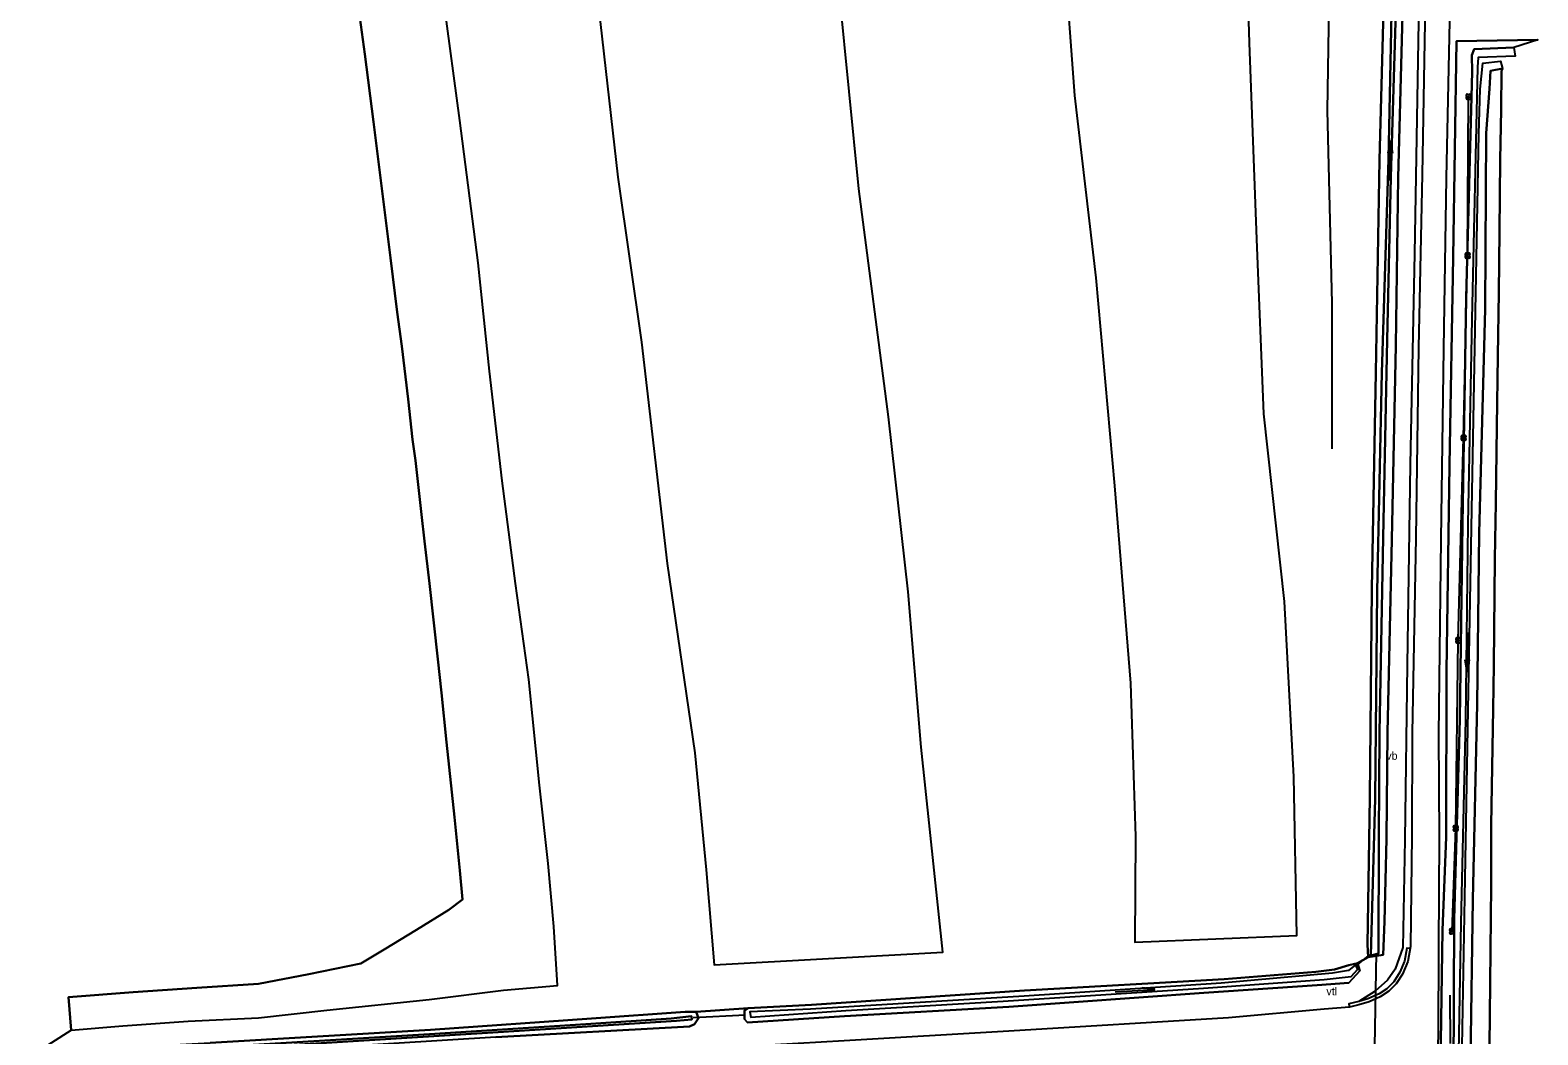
# Model space of a CAD drawing. Extents: x 154825 to 158680, y 370717 to 378075.
# Drawn here: x 157111.2 to 157300.9, y 373273.9 to 373400.2 of the extents above; entities that cross this region are included whole.
import ezdxf

# ---------------------------------------------------------------- set-up
doc = ezdxf.new("R2010")
doc.units = 0
for name, color, linetype in [('boom', 7, 'Continuous'), ('cultuurscheiding', 7, 'Continuous'), ('duiker lijn', 7, 'Continuous'), ('greppel - midden sloot', 7, 'Continuous'), ('hoogteverschillijn', 7, 'Continuous'), ('insteek sloot', 7, 'Continuous'), ('kant onverhard', 7, 'Continuous'), ('maaiveldlijn algemeen - gesloten verharding', 7, 'Continuous'), ('maaiveldlijn algemeen - onverhard', 7, 'Continuous'), ('maaiveldlijn algemeen - verharding algemeen', 7, 'Continuous'), ('raster - hek', 7, 'Continuous'), ('Sloot bodem', 7, 'Continuous'), ('stroomrichting  watergangen', 7, 'Continuous'), ('verkeersb_z kabel', 7, 'Continuous'), ('verklikker transportleiding', 7, 'Continuous'), ('vlak_Bos', 7, 'Continuous'), ('vlak_Grasland', 7, 'Continuous'), ('vlak_Grazige_vegetatie', 7, 'Continuous')]:
    doc.layers.add(name, color=color, linetype=linetype)

msp = doc.modelspace()

# ---------------------------------------------------------------- linework, layer by layer
at = {"layer": 'boom'}
msp.add_lwpolyline([(157290.1, 373286.89), (157290.56, 373299.85), (157290.88, 373323.49), (157291.54, 373348.96), (157292.04, 373371.87), (157292.18, 373391.83)], dxfattribs=at)
for centre in [(157292.18, 373391.83), (157292.04, 373371.87), (157291.54, 373348.96), (157290.88, 373323.49), (157290.56, 373299.85), (157290.1, 373286.89)]:
    msp.add_circle(centre, 0.006, dxfattribs=at)
for centre, start, end in [((157292.02, 373391.99), 357.075, 272.925), ((157292.02, 373391.67), 87.075, 2.925), ((157292.33, 373391.99), 267.075, 182.925), ((157292.33, 373391.67), 177.075, 92.925), ((157291.88, 373372.03), 357.075, 272.925), ((157292.2, 373372.03), 267.075, 182.925), ((157291.88, 373371.71), 87.075, 2.925), ((157292.2, 373371.71), 177.075, 92.925), ((157291.39, 373349.11), 357.075, 272.925), ((157291.39, 373348.8), 87.075, 2.925), ((157291.7, 373349.11), 267.075, 182.925), ((157291.7, 373348.8), 177.075, 92.925), ((157290.72, 373323.64), 357.075, 272.925), ((157290.72, 373323.33), 87.075, 2.925), ((157291.04, 373323.64), 267.075, 182.925), ((157291.04, 373323.33), 177.075, 92.925), ((157290.4, 373300.01), 357.075, 272.925), ((157290.71, 373300.01), 267.075, 182.925), ((157290.4, 373299.69), 87.075, 2.925), ((157290.71, 373299.69), 177.075, 92.925), ((157289.94, 373287.04), 357.075, 272.925), ((157289.94, 373286.73), 87.075, 2.925), ((157290.26, 373287.04), 267.075, 182.925), ((157290.26, 373286.73), 177.075, 92.925)]:
    msp.add_arc(centre, 0.158, start, end, dxfattribs=at)
at = {"layer": 'cultuurscheiding'}
for points in [[(157278.21, 373282.9), (157279.55, 373283.66)], [(157195.01, 373276.76), (157201.55, 373277.22)]]:
    msp.add_lwpolyline(points, dxfattribs=at)
at = {"layer": 'duiker lijn'}
for points in [[(157278.13, 373282.65), (157279.76, 373283.94)], [(157280.53, 373284.15), (157280.26, 373267.78)], [(157194.64, 373276.06), (157201.22, 373276.41)]]:
    msp.add_lwpolyline(points, dxfattribs=at)
at = {"layer": 'greppel - midden sloot'}
msp.add_lwpolyline([(157298.05, 373396.94), (157293.38, 373396.78), (157293.28, 373395.57), (157292.56, 373363.86), (157292.07, 373338.15), (157291.77, 373313.51), (157291.19, 373287.95), (157290.87, 373269.37), (157291.07, 373268.84), (157291.29, 373269.01), (157291.34, 373270.07), (157291.71, 373291.21), (157292.12, 373314.73), (157292.52, 373337.62), (157293.03, 373364.87), (157293.47, 373387.19), (157293.64, 373392.8), (157293.98, 373396.06), (157296.17, 373396.31)], dxfattribs=at)
at = {"layer": 'hoogteverschillijn'}
for points in [[(157241.3, 373409.56), (157242.61, 373392), (157245.26, 373369.07), (157247.63, 373342.93), (157249.65, 373318.12), (157250.28, 373298.8), (157250.18, 373285.54), (157270.58, 373286.38), (157270.18, 373306.31), (157269.01, 373328.39), (157266.42, 373351.96), (157265.53, 373373.94), (157264.63, 373398.61), (157263.96, 373418.94)], [(157274.77, 373413.84), (157274.4, 373390.12), (157274.98, 373365.89), (157274.98, 373347.57)], [(157182.49, 373405.01), (157185.13, 373381.74), (157188.11, 373360.96), (157191.34, 373333.16), (157194.82, 373309.34), (157196.25, 373294.62), (157197.28, 373282.69), (157226.05, 373284.26), (157223.31, 373310.05), (157221.69, 373329.59), (157219.18, 373351.58), (157215.47, 373380.26), (157213.05, 373404.79)], [(157152.57, 373402.71), (157153.3, 373397.18), (157154.39, 373388.68), (157155.06, 373383.32), (157155.67, 373378.62), (157156.54, 373371.57), (157157.39, 373364.73), (157157.96, 373360.46), (157158.78, 373353.8), (157159.33, 373348.72), (157159.68, 373346.11), (157160.45, 373339.33), (157160.84, 373335.95), (157161.47, 373330.62), (157162.49, 373321.12), (157162.97, 373316.88), (157163.6, 373310.69), (157164.6, 373301.26), (157165.27, 373294.54), (157165.62, 373290.91), (157163.89, 373289.62), (157159.83, 373287.09), (157155.77, 373284.61), (157152.83, 373282.84), (157146.29, 373281.53), (157139.93, 373280.29), (157132.17, 373279.79), (157124.19, 373279.25), (157116.04, 373278.63), (157116.39, 373274.47), (157122.88, 373275.03), (157131.11, 373275.61), (157139.95, 373276.02), (157148.55, 373276.98), (157161.42, 373278.32), (157170.77, 373279.48), (157177.55, 373280.08), (157177.11, 373287.49), (157176.37, 373295.44), (157175.3, 373305.29), (157173.93, 373318.57), (157172.26, 373330.64), (157170.59, 373343.54), (157169.01, 373357.35), (157167.56, 373370.95), (157165.25, 373388.84), (157163.28, 373403.5)], [(157294.61, 373258.61), (157294.78, 373268.51), (157294.87, 373280.38), (157295.03, 373292.71), (157295.02, 373300.3), (157295.28, 373314.85), (157295.34, 373320.37), (157295.49, 373333.72), (157295.6, 373340.78), (157295.71, 373350.39), (157295.85, 373359.25), (157295.98, 373367.24), (157296.05, 373374.89), (157296.16, 373383.91), (157296.28, 373390.24), (157296.3, 373395.09)]]:
    msp.add_lwpolyline(points, dxfattribs=at)
at = {"layer": 'insteek sloot'}
for points in [[(157279.55, 373283.66), (157279.46, 373285.25), (157279.73, 373303.74), (157280, 373329.98), (157280.52, 373357.16), (157280.95, 373383.91), (157281.66, 373410.57)], [(157283.92, 373403.67), (157283.31, 373381.69), (157283, 373360.55), (157282.53, 373336.15), (157281.99, 373311.91), (157281.83, 373298.54), (157281.59, 373288.15), (157281.44, 373283.96), (157279.55, 373283.66)], [(157297.85, 373398.03), (157292.86, 373397.8), (157292.6, 373397.08), (157292.62, 373394.95), (157291.87, 373366.61), (157291.4, 373338.11), (157291.09, 373313.52), (157290.37, 373288.41), (157290.26, 373268.67), (157290.92, 373268.5), (157291.89, 373268.71), (157292.41, 373270.71), (157292.7, 373290.92), (157293.24, 373315.47), (157293.49, 373337.02), (157294.25, 373365.11), (157294.38, 373387.25), (157294.82, 373392.82), (157294.94, 373395.1), (157296.43, 373395.37)], [(157278.21, 373282.9), (157278.5, 373281.91), (157277.09, 373280.42), (157273.14, 373280.14), (157258.87, 373279.17), (157234.35, 373277.42), (157213.68, 373276.24), (157201.45, 373275.44), (157201.09, 373275.87), (157201.07, 373276.95), (157201.55, 373277.22)], [(157201.55, 373277.22), (157209.52, 373277.67), (157236.32, 373279.46), (157261.41, 373280.88), (157272.94, 373281.79), (157275.29, 373282.09), (157277.09, 373282.63), (157278.21, 373282.9)], [(157195.01, 373276.76), (157195.28, 373275.96), (157194.8, 373275.22), (157194.15, 373274.93), (157169.78, 373273.57), (157143.46, 373271.96), (157121.39, 373270.57), (157111.21, 373270.08)], [(157111.96, 373271.64), (157133.88, 373272.88), (157161.56, 373274.53), (157181.83, 373275.94), (157193.61, 373276.79), (157195.01, 373276.76)]]:
    msp.add_lwpolyline(points, dxfattribs=at)
at = {"layer": 'kant onverhard'}
msp.add_lwpolyline([(157300.88, 373399.01), (157290.65, 373398.84)], dxfattribs=at)
at = {"layer": 'maaiveldlijn algemeen - gesloten verharding'}
for points in [[(157287.62, 373451.56), (157286.97, 373427.74), (157286.71, 373403.55), (157286.34, 373382.08), (157285.87, 373360.32), (157285.54, 373336.36), (157285.09, 373311.86), (157285.04, 373298.94), (157284.85, 373285), (157284.51, 373283.09), (157283.84, 373281.51), (157283.08, 373280.3), (157282.12, 373279.38), (157281.05, 373278.65), (157279.67, 373278.05), (157278.36, 373277.65), (157277.18, 373277.38)], [(157290.73, 373451.57), (157290.27, 373427.19), (157289.8, 373403.3), (157289.37, 373381.66), (157289.01, 373360.15), (157288.66, 373336.15), (157288.38, 373311.65), (157288.48, 373298.66), (157288.39, 373284.94), (157288.35, 373273.86), (157287.89, 373261.66), (157287.56, 373253.44), (157287.8, 373252.82)], [(157277.18, 373277.38), (157274.01, 373277.09), (157261.95, 373276.03), (157234.32, 373274.34), (157213.62, 373273.13), (157193.36, 373271.94), (157169.76, 373270.59), (157143.66, 373268.97), (157121.64, 373267.67), (157111.83, 373267.05)]]:
    msp.add_lwpolyline(points, dxfattribs=at)
at = {"layer": 'maaiveldlijn algemeen - onverhard'}
for points in [[(157286.91, 373452.88), (157286.28, 373426.51), (157285.84, 373398.84), (157285.37, 373372.14), (157284.82, 373345.6), (157284.43, 373320.39), (157284.15, 373298.43), (157283.91, 373284.88), (157282.95, 373282.12), (157281.95, 373280.75), (157280.4, 373279.39), (157278.36, 373278.06)], [(157290.65, 373398.84), (157290.23, 373371.65), (157289.77, 373345.53), (157289.39, 373319.6), (157289.33, 373298.74), (157288.91, 373287.06), (157288.54, 373264.58), (157287.8, 373252.82)]]:
    msp.add_lwpolyline(points, dxfattribs=at)
at = {"layer": 'maaiveldlijn algemeen - verharding algemeen'}
for points in [[(157284.82, 373284.75), (157284.42, 373284.77), (157284.11, 373283.16), (157283.51, 373281.76), (157282.77, 373280.56), (157281.89, 373279.66), (157280.93, 373279.05), (157279.48, 373278.39), (157278.36, 373278.06)], [(157278.36, 373278.06), (157277.09, 373277.78), (157277.18, 373277.38)]]:
    msp.add_lwpolyline(points, dxfattribs=at)
at = {"layer": 'raster - hek'}
msp.add_lwpolyline([(157289.88, 373272.79), (157289.87, 373278.85)], dxfattribs=at)
at = {"layer": 'Sloot bodem'}
for points in [[(157283.92, 373451.9), (157283.34, 373428.36), (157283.05, 373403.99), (157282.4, 373381.72), (157281.94, 373361.28), (157281.43, 373336.42), (157280.96, 373311.9), (157280.86, 373298.76), (157280.84, 373284.13), (157279.87, 373283.87), (157279.91, 373285.42), (157280.4, 373303.59), (157280.68, 373329.65), (157281.26, 373357.17), (157282.08, 373383.96), (157282.63, 373410.47), (157283.01, 373435.14), (157283.51, 373459.34)], [(157274.02, 373280.86), (157277.38, 373281.22), (157278.23, 373282.14), (157277.95, 373282.68), (157277.06, 373281.97), (157275.04, 373281.62), (157261.06, 373280.37), (157236.25, 373278.76), (157209.37, 373277.09), (157201.75, 373276.77), (157201.88, 373276.09), (157213.83, 373276.94), (157233.62, 373278.1), (157258.82, 373279.77), (157274.02, 373280.86)], [(157112.39, 373271.01), (157133.73, 373272.28), (157161.45, 373273.98), (157181.14, 373275.21), (157191.85, 373275.95), (157194.41, 373276.21), (157194.44, 373275.8), (157192.53, 373275.66), (157170.09, 373274.21), (157143.76, 373272.6), (157121.65, 373271.24), (157111.25, 373270.65)]]:
    msp.add_lwpolyline(points, dxfattribs=at)
at = {"layer": 'stroomrichting  watergangen'}
for p, q in [((157282.3, 373386.3), (157282.02, 373384.75)), ((157282.29, 373381.32), (157282.31, 373386.32)), ((157282.31, 373386.32), (157282.58, 373384.76)), ((157292.03, 373324.46), (157292.01, 373319.47)), ((157292.01, 373319.47), (157291.74, 373321.02)), ((157292.02, 373319.48), (157292.3, 373321.03)), ((157247.71, 373279.29), (157252.7, 373279.59)), ((157252.68, 373279.6), (157251.11, 373279.78)), ((157252.7, 373279.59), (157251.16, 373279.22))]:
    msp.add_line(p, q, dxfattribs=at)
at = {"layer": 'vlak_Bos'}
msp.add_lwpolyline([(157292.41, 373270.71), (157292.7, 373290.92), (157293.24, 373315.47), (157293.49, 373337.02), (157294.25, 373365.11), (157294.38, 373387.25), (157294.82, 373392.82), (157294.94, 373395.1), (157296.43, 373395.37), (157296.3, 373395.09), (157296.28, 373390.24), (157296.16, 373383.91), (157296.05, 373374.89), (157295.98, 373367.24), (157295.85, 373359.25), (157295.71, 373350.39), (157295.6, 373340.78), (157295.49, 373333.72), (157295.34, 373320.37), (157295.28, 373314.85), (157295.02, 373300.3), (157295.03, 373292.71), (157294.87, 373280.38), (157294.78, 373268.51)], dxfattribs=at)
at = {"layer": 'vlak_Grasland'}
for points in [[(157281.66, 373410.57), (157280.95, 373383.91), (157280.52, 373357.16), (157280, 373329.98), (157279.73, 373303.74), (157279.46, 373285.25), (157279.55, 373283.66), (157278.21, 373282.9), (157277.09, 373282.63), (157275.29, 373282.09), (157272.94, 373281.79), (157261.41, 373280.88), (157236.32, 373279.46), (157209.52, 373277.67), (157201.55, 373277.22), (157195.01, 373276.76), (157193.61, 373276.79), (157181.83, 373275.94), (157161.56, 373274.53), (157133.88, 373272.88)], [(157111.96, 373271.64), (157116.39, 373274.47), (157116.04, 373278.63), (157124.19, 373279.25), (157132.17, 373279.79), (157139.93, 373280.29), (157146.29, 373281.53), (157152.83, 373282.84), (157155.77, 373284.61), (157159.83, 373287.09), (157163.89, 373289.62), (157165.62, 373290.91), (157165.27, 373294.54), (157164.6, 373301.26), (157163.6, 373310.69), (157162.97, 373316.88), (157162.49, 373321.12), (157161.47, 373330.62), (157160.84, 373335.95), (157160.45, 373339.33), (157159.68, 373346.11), (157159.33, 373348.72), (157158.78, 373353.8), (157157.96, 373360.46), (157157.39, 373364.73), (157156.54, 373371.57), (157155.67, 373378.62), (157155.06, 373383.32), (157154.39, 373388.68), (157153.3, 373397.18), (157152.57, 373402.71)]]:
    msp.add_lwpolyline(points, dxfattribs=at)
at = {"layer": 'vlak_Grazige_vegetatie'}
for points in [[(157286.28, 373426.51), (157285.84, 373398.84), (157285.37, 373372.14), (157284.82, 373345.6), (157284.43, 373320.39), (157284.15, 373298.43), (157283.91, 373284.88), (157282.95, 373282.12), (157281.95, 373280.75), (157280.4, 373279.39), (157278.36, 373278.06), (157277.09, 373277.78), (157277.18, 373277.38), (157274.01, 373277.09), (157261.95, 373276.03), (157234.32, 373274.34), (157213.62, 373273.13)], [(157283.92, 373403.67), (157283.31, 373381.69), (157283, 373360.55), (157282.53, 373336.15), (157281.99, 373311.91), (157281.83, 373298.54), (157281.59, 373288.15), (157281.44, 373283.96), (157279.55, 373283.66), (157279.46, 373285.25), (157279.73, 373303.74), (157280, 373329.98), (157280.52, 373357.16), (157280.95, 373383.91), (157281.66, 373410.57)], [(157282.63, 373410.47), (157282.08, 373383.96), (157281.26, 373357.17), (157280.68, 373329.65), (157280.4, 373303.59), (157279.91, 373285.42), (157279.87, 373283.87), (157280.84, 373284.13), (157280.86, 373298.76), (157280.96, 373311.9), (157281.43, 373336.42), (157281.94, 373361.28), (157282.4, 373381.72), (157283.05, 373403.99)], [(157169.78, 373273.57), (157194.15, 373274.93), (157194.8, 373275.22), (157195.28, 373275.96), (157195.01, 373276.76), (157201.55, 373277.22), (157201.07, 373276.95), (157201.09, 373275.87), (157201.45, 373275.44), (157213.68, 373276.24), (157234.35, 373277.42), (157258.87, 373279.17), (157273.14, 373280.14), (157277.09, 373280.42), (157278.5, 373281.91), (157278.21, 373282.9), (157279.55, 373283.66), (157281.44, 373283.96), (157281.59, 373288.15), (157281.83, 373298.54), (157281.99, 373311.91), (157282.53, 373336.15), (157283, 373360.55), (157283.31, 373381.69), (157283.92, 373403.67)], [(157288.54, 373264.58), (157288.91, 373287.06), (157289.33, 373298.74), (157289.39, 373319.6), (157289.77, 373345.53), (157290.23, 373371.65), (157290.65, 373398.84), (157300.88, 373399.01), (157297.85, 373398.03), (157292.86, 373397.8), (157292.6, 373397.08), (157292.62, 373394.95), (157291.87, 373366.61), (157291.4, 373338.11), (157291.09, 373313.52), (157290.37, 373288.41), (157290.26, 373268.67)], [(157290.26, 373268.67), (157290.37, 373288.41), (157291.09, 373313.52), (157291.4, 373338.11), (157291.87, 373366.61), (157292.62, 373394.95), (157292.6, 373397.08), (157292.86, 373397.8), (157297.85, 373398.03), (157298.05, 373396.94), (157293.38, 373396.78), (157293.28, 373395.57), (157292.56, 373363.86), (157292.07, 373338.15), (157291.77, 373313.51), (157291.19, 373287.95), (157290.87, 373269.37)], [(157291.34, 373270.07), (157291.71, 373291.21), (157292.12, 373314.73), (157292.52, 373337.62), (157293.03, 373364.87), (157293.47, 373387.19), (157293.64, 373392.8), (157293.98, 373396.06), (157296.17, 373396.31), (157296.43, 373395.37), (157294.94, 373395.1), (157294.82, 373392.82), (157294.38, 373387.25), (157294.25, 373365.11), (157293.49, 373337.02), (157293.24, 373315.47), (157292.7, 373290.92), (157292.41, 373270.71)], [(157143.76, 373272.6), (157170.09, 373274.21), (157192.53, 373275.66), (157194.44, 373275.8), (157194.41, 373276.21), (157191.85, 373275.95), (157181.14, 373275.21), (157161.45, 373273.98), (157133.73, 373272.28)], [(157133.88, 373272.88), (157161.56, 373274.53), (157181.83, 373275.94), (157193.61, 373276.79), (157195.01, 373276.76), (157195.28, 373275.96), (157194.8, 373275.22), (157194.15, 373274.93), (157169.78, 373273.57)]]:
    msp.add_lwpolyline(points, dxfattribs=at)
for points in [[(157278.21, 373282.9), (157278.5, 373281.91), (157277.09, 373280.42), (157273.14, 373280.14), (157258.87, 373279.17), (157234.35, 373277.42), (157213.68, 373276.24), (157201.45, 373275.44), (157201.09, 373275.87), (157201.07, 373276.95), (157201.55, 373277.22), (157209.52, 373277.67), (157236.32, 373279.46), (157261.41, 373280.88), (157272.94, 373281.79), (157275.29, 373282.09), (157277.09, 373282.63)], [(157201.75, 373276.77), (157201.88, 373276.09), (157213.83, 373276.94), (157233.62, 373278.1), (157258.82, 373279.77), (157274.02, 373280.86), (157277.38, 373281.22), (157278.23, 373282.14), (157277.95, 373282.68), (157277.06, 373281.97), (157275.04, 373281.62), (157261.06, 373280.37), (157236.25, 373278.76), (157209.37, 373277.09)]]:
    msp.add_lwpolyline(points, close=True, dxfattribs=at)

# ---------------------------------------------------------------- texts
at = {"layer": 'verkeersb_z kabel'}
msp.add_text('vb', height=1, dxfattribs=at).set_placement((157281.82, 373308.47))
at = {"layer": 'verklikker transportleiding'}
msp.add_text('vtl', height=1, dxfattribs=at).set_placement((157274.29, 373278.86))

doc.saveas('drawing.dxf')
